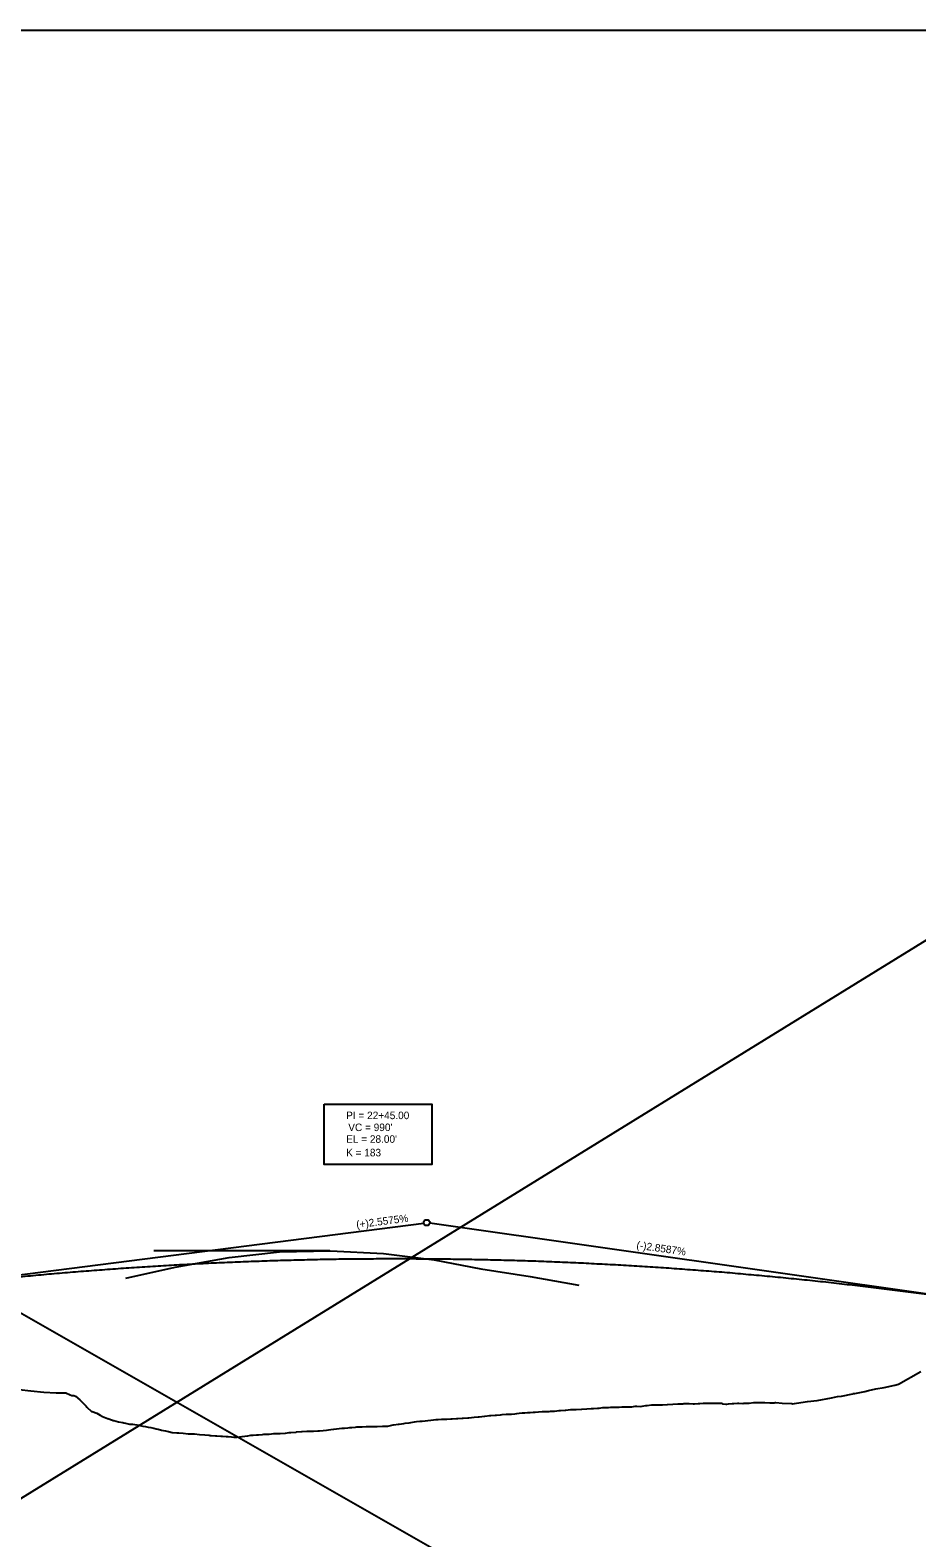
# Model space of a CAD drawing. Extents: x 1626634 to 1638383, y 876896 to 886347.
# Drawn here: x 1628678 to 1629503, y 882354 to 883757 of the extents above; entities that cross this region are included whole.
import ezdxf

# ---------------------------------------------------------------- set-up
doc = ezdxf.new("R2010")
doc.units = 0
for name, color, linetype in [('Exist Vertical Profile Ground Line', 7, 'Continuous'), ('Prop Vertical Profile Curve Label', 7, 'Continuous'), ('Prop Vertical Profile Grade', 7, 'Continuous'), ('Prop Vertical Profile Grade Label', 7, 'Continuous'), ('Prop VPI Label', 7, 'Continuous'), ('Raster_Level_0', 7, 'Continuous')]:
    doc.layers.add(name, color=color, linetype=linetype)

msp = doc.modelspace()

# ---------------------------------------------------------------- linework, layer by layer
at = {"layer": 'Exist Vertical Profile Ground Line'}
msp.add_lwpolyline([(1628667.4, 882492), (1628678.4, 882491), (1628690.3, 882489.6), (1628701.8, 882489), (1628710.7, 882488.9), (1628714.8, 882487.3), (1628716.5, 882486.6), (1628718.4, 882486.5), (1628719.8, 882485.9), (1628723.7, 882482.5), (1628724.8, 882481.6), (1628729, 882477.3), (1628729.8, 882476.5), (1628730.5, 882475.8), (1628734.8, 882471.7), (1628735.2, 882471.5), (1628739.8, 882470), (1628742.7, 882468.3), (1628744.8, 882467.1), (1628749.5, 882465.2), (1628749.8, 882465.1), (1628754.2, 882463.5), (1628754.8, 882463.3), (1628755.6, 882463.2), (1628759.9, 882462.1), (1628763.7, 882461.5), (1628764.9, 882461.2), (1628766.2, 882460.9), (1628769.9, 882460), (1628773.1, 882459.8), (1628774.9, 882459.5), (1628776.8, 882459.2), (1628779.9, 882458.7), (1628782.6, 882458.1), (1628784.9, 882457.7), (1628787.4, 882457.1), (1628789.9, 882456.6), (1628792.8, 882456), (1628794.9, 882455.5), (1628796.8, 882455.1), (1628799.9, 882454.3), (1628803.4, 882453.7), (1628804.9, 882453.2), (1628806.3, 882453.1), (1628809.9, 882452.1), (1628814, 882451.9), (1628814.9, 882451.9), (1628815.8, 882451.9), (1628820, 882451.5), (1628824.6, 882450.9), (1628825, 882450.9), (1628830, 882451), (1628830.6, 882450.9), (1628835.2, 882450.3), (1628840, 882449.9), (1628844.2, 882449.5), (1628845, 882449.4), (1628845.9, 882449.3), (1628850, 882449.1), (1628851.2, 882449), (1628855, 882448.7), (1628856.5, 882448.6), (1628860, 882448.5), (1628861.8, 882448.3), (1628865, 882448), (1628867.1, 882447.9), (1628870, 882447.9), (1628872.4, 882448), (1628875, 882448.4), (1628877.4, 882448.7), (1628880, 882449), (1628883, 882449.5), (1628885.1, 882449.6), (1628888.3, 882449.9), (1628890.1, 882450), (1628893.7, 882450.3), (1628895.1, 882450.4), (1628896.3, 882450.5), (1628900.1, 882450.6), (1628904.3, 882451.2), (1628905.1, 882451.3), (1628909.6, 882451.3), (1628910.1, 882451.3), (1628915.3, 882451.6), (1628918.6, 882452), (1628920.2, 882452.1), (1628925.1, 882452.5), (1628925.5, 882452.6), (1628930.1, 882453), (1628930.8, 882453), (1628935.1, 882453.2), (1628936.1, 882453.3), (1628940.1, 882453.3), (1628941.4, 882453.4), (1628945.2, 882453.5), (1628946.8, 882453.6), (1628950.2, 882454), (1628953.2, 882454.3), (1628955.2, 882454.5), (1628957.4, 882454.8), (1628960.2, 882455.2), (1628962.7, 882455.5), (1628965.2, 882455.7), (1628968, 882456.1), (1628970.2, 882456.1), (1628973.3, 882456.4), (1628975.2, 882456.8), (1628976.9, 882456.8), (1628980.2, 882457.2), (1628981.6, 882457.3), (1628985.2, 882457.4), (1628986.4, 882457.4), (1628990.2, 882457.6), (1628994.6, 882457.8), (1628995.2, 882457.8), (1628995.8, 882457.8), (1629000.2, 882457.8), (1629000.6, 882457.8), (1629005.3, 882458), (1629006.5, 882458), (1629010.5, 882458.1), (1629015.3, 882459.1), (1629015.8, 882459.1), (1629020.3, 882459.8), (1629021.1, 882459.9), (1629025.3, 882460.5), (1629026.4, 882460.7), (1629030.3, 882461.2), (1629031.7, 882461.3), (1629035.3, 882462), (1629037, 882462.2), (1629040.3, 882462.6), (1629042.4, 882462.8), (1629045.3, 882463.1), (1629047.7, 882463.4), (1629050.3, 882463.7), (1629053, 882463.8), (1629055.3, 882464.1), (1629057.4, 882464.1), (1629060.3, 882464.4), (1629063.6, 882464.6), (1629065.3, 882464.6), (1629068.9, 882464.8), (1629070.4, 882464.9), (1629074.2, 882465.2), (1629075.4, 882465.2), (1629079.5, 882465.4), (1629080.4, 882465.4), (1629084.8, 882465.8), (1629085.4, 882465.9), (1629085.9, 882465.9), (1629090.6, 882466.4), (1629094.4, 882466.7), (1629095.5, 882466.8), (1629100.4, 882467.3), (1629100.8, 882467.3), (1629105.4, 882467.9), (1629106.1, 882467.9), (1629110.4, 882468.2), (1629111.4, 882468.3), (1629115.4, 882468.6), (1629116.7, 882468.7), (1629120.4, 882469.1), (1629123.8, 882469.2), (1629125.4, 882469.3), (1629128.5, 882469.6), (1629130.5, 882469.9), (1629132.6, 882470.1), (1629135.5, 882470.3), (1629137.9, 882470.5), (1629140.5, 882470.6), (1629142.7, 882470.7), (1629145.5, 882470.9), (1629147.5, 882471), (1629150.5, 882471.2), (1629153.9, 882471.5), (1629155.5, 882471.5), (1629156.9, 882471.7), (1629160.5, 882471.7), (1629161.7, 882471.9), (1629165.5, 882471.9), (1629169.8, 882472.6), (1629170.5, 882472.7), (1629171.2, 882472.7), (1629175.5, 882473), (1629175.9, 882473), (1629180.5, 882473.4), (1629182.4, 882473.4), (1629185.7, 882473.5), (1629190.6, 882473.8), (1629191, 882473.8), (1629195.6, 882474.2), (1629199.6, 882474.4), (1629200.6, 882474.4), (1629201.7, 882474.5), (1629205.6, 882474.7), (1629207, 882474.8), (1629210.6, 882475.3), (1629212.3, 882475.3), (1629215.6, 882475.5), (1629217.6, 882475.7), (1629220.6, 882475.7), (1629222.9, 882475.7), (1629225.6, 882475.8), (1629228.2, 882475.9), (1629230.6, 882476), (1629233.5, 882475.9), (1629235.6, 882476.1), (1629237.5, 882476), (1629240.6, 882476.6), (1629242.2, 882476.5), (1629245.6, 882476.3), (1629247, 882476.5), (1629250.6, 882477.3), (1629251.7, 882477.3), (1629255.7, 882477.7), (1629256.4, 882477.7), (1629260.7, 882477.9), (1629261.2, 882477.9), (1629265.9, 882478), (1629270.3, 882478.2), (1629270.7, 882478.2), (1629275.7, 882478.6), (1629280.1, 882478.9), (1629280.7, 882478.9), (1629284.9, 882478.9), (1629285.7, 882479), (1629289.6, 882479), (1629290.7, 882479), (1629294.4, 882478.8), (1629295.7, 882478.7), (1629299.1, 882479), (1629300.7, 882479.2), (1629303.8, 882479.3), (1629305.7, 882479.4), (1629308.6, 882479.4), (1629310.7, 882479.5), (1629313.3, 882479.4), (1629315.8, 882479.3), (1629318, 882479.3), (1629320.8, 882479.3), (1629321.8, 882478.9), (1629324.9, 882478.4), (1629325.8, 882478.6), (1629327.5, 882478.7), (1629330.8, 882479.1), (1629332.3, 882479.2), (1629335.8, 882479.5), (1629337, 882479.4), (1629340.8, 882479.2), (1629341.7, 882479.4), (1629345.8, 882479.4), (1629346.5, 882479.5), (1629350.8, 882479.9), (1629351.2, 882479.9), (1629355.9, 882479.9), (1629358.2, 882479.9), (1629361.1, 882479.9), (1629365.8, 882479.8), (1629369.9, 882479.8), (1629370.8, 882480), (1629371.3, 882479.9), (1629377.2, 882479.3), (1629386.4, 882479), (1629387.4, 882478.9), (1629388.7, 882479), (1629398.8, 882480.6), (1629401, 882481), (1629410, 882481.9), (1629423.1, 882484.4), (1629428.9, 882485.6), (1629432.5, 882486), (1629443.1, 882488.2), (1629443.5, 882488.3), (1629444.8, 882488.5), (1629454.1, 882490.2), (1629457.7, 882491.1), (1629464.5, 882492.7), (1629472.2, 882494.1), (1629482.1, 882496.2), (1629485.7, 882497.2), (1629506.5, 882508.9)], dxfattribs=at)
at = {"layer": 'Prop Vertical Profile Curve Label'}
for p, q in [((1630183.7, 883324.8), (1627555.3, 881704.1)), ((1627641.7, 883149.2), (1630183.7, 881699)), ((1628956.6, 882621.2), (1628792.8, 882621.2))]:
    msp.add_line(p, q, dxfattribs=at)
msp.add_lwpolyline([(1626634.5, 883757.1), (1630394.5, 883757.1), (1630394.5, 881162.5), (1626634.5, 881162.5)], close=True, dxfattribs=at)
at = {"layer": 'Prop Vertical Profile Grade'}
msp.add_spline([(1628551.6, 882584.1), (1628571.4, 882586.5), (1628591.2, 882588.9), (1628611, 882591.2), (1628630.8, 882593.3), (1628650.6, 882595.4), (1628670.4, 882597.3), (1628690.2, 882599.2), (1628710, 882600.9), (1628729.8, 882602.5), (1628749.6, 882604), (1628769.4, 882605.4), (1628789.2, 882606.7), (1628809, 882607.9), (1628828.8, 882609), (1628848.6, 882610), (1628868.4, 882610.8), (1628888.2, 882611.6), (1628908, 882612.3), (1628927.8, 882612.8), (1628947.6, 882613.3), (1628967.4, 882613.6), (1628987.2, 882613.8), (1629007, 882613.9), (1629026.8, 882613.9), (1629046.6, 882613.8), (1629066.4, 882613.6), (1629086.2, 882613.3), (1629106, 882612.9), (1629125.8, 882612.4), (1629145.6, 882611.8), (1629165.4, 882611), (1629185.2, 882610.2), (1629205, 882609.2), (1629224.8, 882608.2), (1629244.6, 882607), (1629264.4, 882605.7), (1629284.2, 882604.3), (1629304, 882602.8), (1629323.8, 882601.3), (1629343.6, 882599.5), (1629363.4, 882597.7), (1629383.2, 882595.8), (1629403, 882593.8), (1629422.8, 882591.7), (1629442.6, 882589.4), (1629462.4, 882587.1), (1629482.2, 882584.6), (1629502, 882582.1), (1629521.8, 882579.4), (1629541.6, 882576.6)], degree=3, dxfattribs=at)
at = {"layer": 'Prop VPI Label'}
for p, q in [((1628551.6, 882584.1), (1629043.9, 882647)), ((1629541.6, 882576.6), (1629049.4, 882647))]:
    msp.add_line(p, q, dxfattribs=at)
msp.add_lwpolyline([(1628951.3, 882757.5), (1629051.3, 882757.5), (1629051.3, 882701.4), (1628951.3, 882701.4)], close=True, dxfattribs=at)
msp.add_lwpolyline([(1628951.3, 882757.5), (1629051.3, 882757.5), (1629051.3, 882701.4), (1628951.3, 882701.4)], close=True, dxfattribs=at)
msp.add_circle((1629046.6, 882647.4), 2.75, dxfattribs=at)
at = {"layer": 'Raster_Level_0'}
msp.add_lwpolyline([(1628766.6, 882595.6), (1628812.4, 882606.1), (1628862.8, 882614.9), (1628909.5, 882620.2), (1628957.1, 882621.2), (1629006.4, 882618.6), (1629053.6, 882612.8), (1629097, 882604.3), (1629142.7, 882597.3), (1629188.1, 882589.2)], dxfattribs=at)

# ---------------------------------------------------------------- texts
at = {"layer": 'Prop Vertical Profile Curve Label'}
for s, p in [("VC = 990'", (1628973.6, 882732.6)), ('K = 183', (1628971.6, 882709.1))]:
    msp.add_text(s, height=7, dxfattribs=at).set_placement(p)
at = {"layer": 'Prop Vertical Profile Grade Label'}
for s, rotation, p in [('(+)2.5575%', 7.2872, (1628981.5, 882642.1)), ('(-)2.8587%', 351.8654, (1629241.4, 882623.3))]:
    msp.add_text(s, height=7, rotation=rotation, dxfattribs=at).set_placement(p)
at = {"layer": 'Prop VPI Label'}
for s, p in [('PI = 22+45.00', (1628971.6, 882743.7)), ("EL = 28.00'", (1628971.6, 882721.7))]:
    msp.add_text(s, height=7, dxfattribs=at).set_placement(p)

doc.saveas('drawing.dxf')
